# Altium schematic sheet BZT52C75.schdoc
size 127 x 101 mm
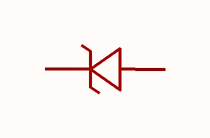
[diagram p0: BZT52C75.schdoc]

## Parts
D?  bzt52c75  [SOD-123_L2.7-W1.7-LS3.8-RD]  (value not drawn)

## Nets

Not connected (* = marked no-connect by the designer): D? 1(K) 2(A)

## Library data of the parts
D? = bzt52c75: 二极管配置:1个独立式;稳压值(标称值):75V;稳压值(范围):71.25V~78.75V;耗散功率(Pd):500mW;; Manufacturer: MDD(辰达半导体); AddInBom: yes; ModelId: b455d3bf1dad47d3a75f9a76b08071c6; ModelTransform: 145.669,64.961,0,0,0,0,0,0,0; Diode Configuration: 1个独立式; Zener Voltage(Nom): 75V; Reverse Leakage Current (Ir): 200nA@57V; Pd - Power Dissipation: 500mW; Impedance(Zzt): 300Ω; Tolerance: ±5%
